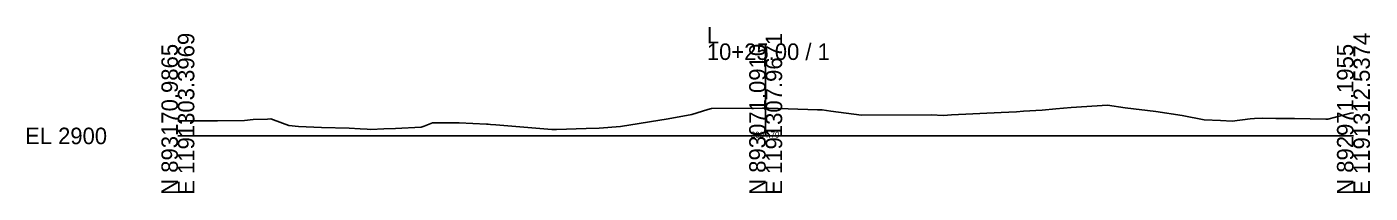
# Model space of a CAD drawing. Extents: x -26 to 203, y -10 to 7027.
# Drawn here: x -25.7 to 202.8, y 490.3 to 518.5 of the extents above; entities that cross this region are included whole.
import ezdxf

# ---------------------------------------------------------------- set-up
doc = ezdxf.new("R2010")
doc.units = 0
for name, color, linetype in [('Default', 7, 'Continuous'), ('Exist Cross Section Cell', 7, 'Continuous'), ('Prop CMT Pvmt Course 3 Wedge', 7, 'Continuous'), ('Scratch_Level_6', 7, 'Continuous')]:
    doc.layers.add(name, color=color, linetype=linetype)

msp = doc.modelspace()

# ---------------------------------------------------------------- linework, layer by layer
at = {"layer": 'Exist Cross Section Cell'}
for p, q in [((100, 500), (100, 515.68)), ((0, 500), (100, 500)), ((100, 500), (200, 500))]:
    msp.add_line(p, q, dxfattribs=at)
at = {"layer": 'Prop CMT Pvmt Course 3 Wedge'}
for p, q in [((151.99, 504.83), (158.15, 505.23)), ((158.15, 505.23), (161.16, 504.78)), ((12.82, 502.76), (15.24, 502.86)), ((15.24, 502.86), (15.83, 502.88)), ((15.83, 502.88), (16.26, 502.72)), ((75.31, 501.62), (83.44, 502.92)), ((83.44, 502.92), (87.46, 503.63)), ((87.46, 503.63), (90.18, 504.48)), ((90.18, 504.48), (90.81, 504.67)), ((90.81, 504.67), (99.47, 504.7)), ((99.47, 504.7), (100, 504.7)), ((100, 504.7), (100.49, 504.7)), ((100.49, 504.7), (108.83, 504.44)), ((108.83, 504.44), (109.64, 504.42)), ((109.64, 504.42), (111.08, 504.22)), ((111.08, 504.22), (116.28, 503.52)), ((116.28, 503.52), (128.18, 503.57)), ((128.18, 503.57), (130.24, 503.48)), ((130.24, 503.48), (131.59, 503.58)), ((131.59, 503.58), (140.07, 503.97)), ((140.07, 503.97), (142.68, 504.07)), ((142.68, 504.07), (143.86, 504.17)), ((143.86, 504.17), (147.02, 504.39)), ((147.02, 504.39), (149.38, 504.59)), ((149.38, 504.59), (151.99, 504.83)), ((161.16, 504.78), (166.37, 504.12)), ((166.37, 504.12), (170.85, 503.46)), ((170.85, 503.46), (174.59, 502.72)), ((179.35, 502.5), (182.45, 502.9)), ((182.45, 502.9), (183.16, 502.98)), ((183.16, 502.98), (184.46, 502.99)), ((184.46, 502.99), (186.8, 502.98)), ((186.8, 502.98), (188.31, 502.97)), ((188.31, 502.97), (189.99, 502.96)), ((189.99, 502.96), (195.3, 502.82)), ((195.3, 502.82), (195.67, 502.82)), ((195.67, 502.82), (199.56, 503.83)), ((199.56, 503.83), (200, 503.9)), ((0, 502.57), (1.08, 502.58)), ((1.08, 502.58), (6.72, 502.58)), ((6.72, 502.58), (11.35, 502.61)), ((11.35, 502.61), (12.82, 502.76)), ((16.26, 502.72), (18.88, 501.75)), ((18.88, 501.75), (20.53, 501.61)), ((20.53, 501.61), (24.41, 501.44)), ((24.41, 501.44), (29.16, 501.29)), ((29.16, 501.29), (31, 501.18)), ((31, 501.18), (32.23, 501.17)), ((32.23, 501.17), (32.84, 501.1)), ((32.84, 501.1), (35.05, 501.19)), ((35.05, 501.19), (37.05, 501.25)), ((37.05, 501.25), (41.39, 501.46)), ((41.39, 501.46), (41.89, 501.63)), ((41.89, 501.63), (43.33, 502.19)), ((43.33, 502.19), (45.3, 502.2)), ((45.3, 502.2), (47.83, 502.19)), ((47.83, 502.19), (52.51, 502)), ((52.51, 502), (52.81, 501.99)), ((52.81, 501.99), (53.21, 501.96)), ((53.21, 501.96), (54.11, 501.88)), ((54.11, 501.88), (63.61, 501.07)), ((63.61, 501.07), (64.43, 501.09)), ((64.43, 501.09), (69.46, 501.27)), ((69.46, 501.27), (71.67, 501.34)), ((71.67, 501.34), (75.31, 501.62)), ((174.59, 502.72), (177.39, 502.59)), ((177.39, 502.59), (179.35, 502.5))]:
    msp.add_line(p, q, dxfattribs=at)

# ---------------------------------------------------------------- texts
at = {"layer": 'Default'}
msp.add_text('-', height=0.0001, dxfattribs=at).set_placement((0, 500))
at = {"layer": 'Exist Cross Section Cell'}
for s, p in [('E 1191303.3969', (2.8, 490)), ('E 1191307.9671', (102.8, 490)), ('E 1191312.5374', (202.8, 490)), ('N 893170.9865', (0, 490)), ('N 893071.0910', (100, 490)), ('N 892971.1955', (200, 490))]:
    msp.add_text(s, height=2.8, rotation=90, dxfattribs=at).set_placement(p)
for s, p in [('L', (90, 515.68)), ('10+25.00 / 1', (90, 512.88)), ('EL 2900', (-26, 498.6))]:
    msp.add_text(s, height=2.8, dxfattribs=at).set_placement(p)
at = {"layer": 'Scratch_Level_6'}
msp.add_text('2904.70', height=1, dxfattribs=at).set_placement((97.49, 499.7))

doc.saveas('drawing.dxf')
